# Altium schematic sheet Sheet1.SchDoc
size A4
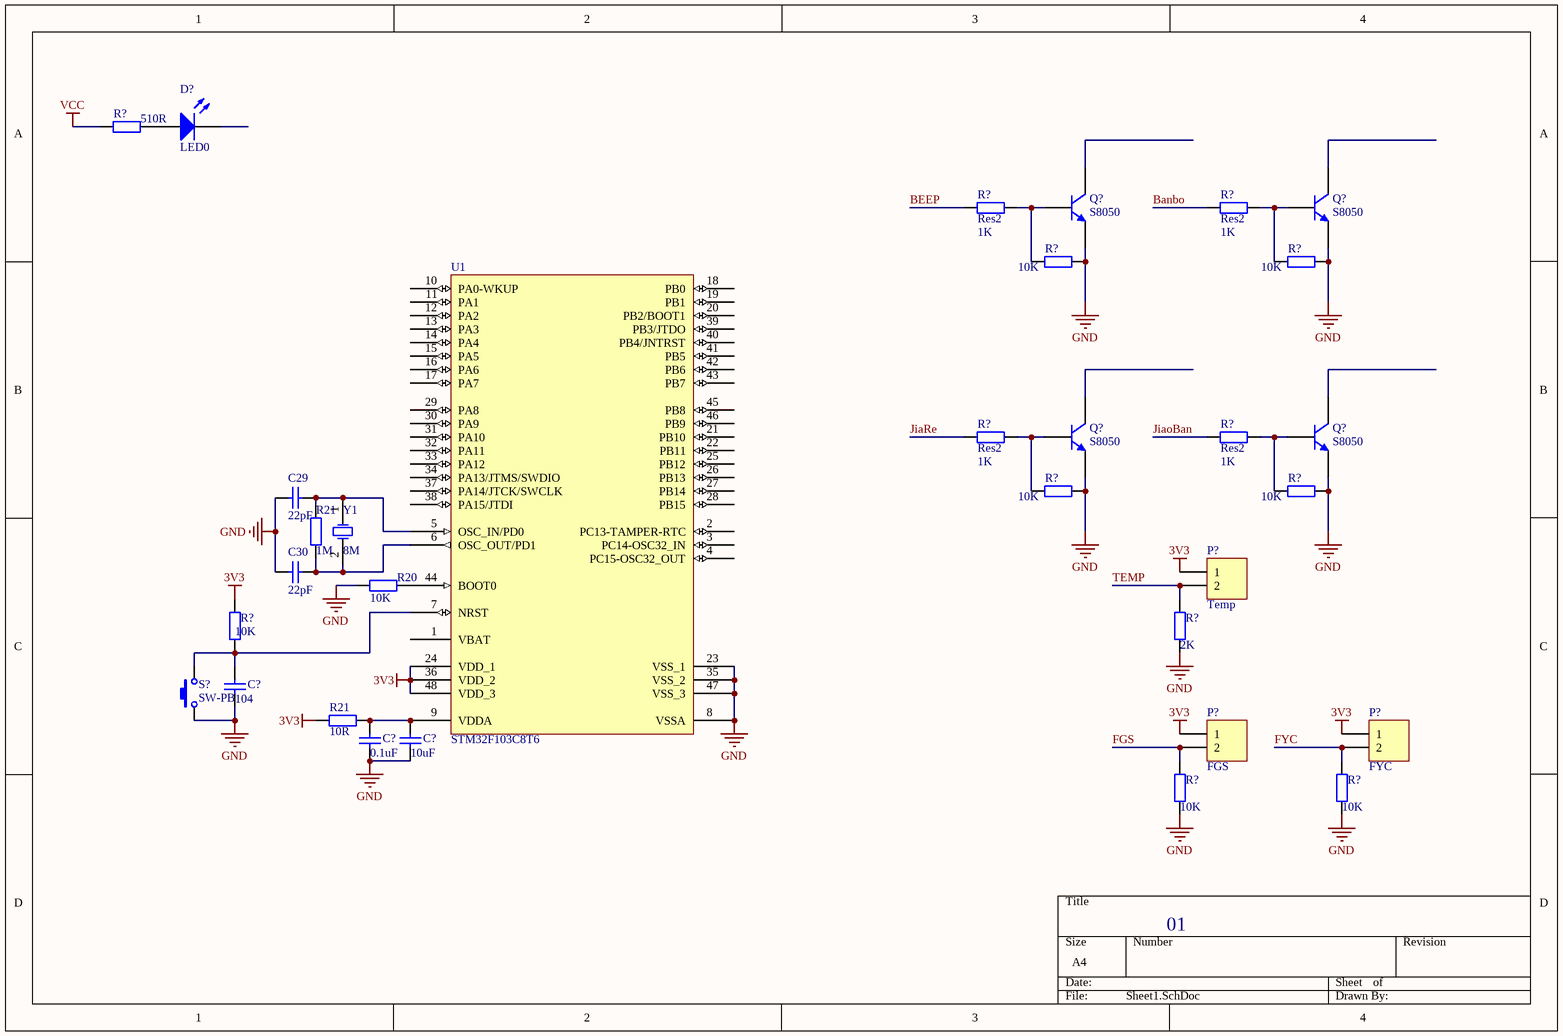
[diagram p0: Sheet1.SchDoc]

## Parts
(Parts that share a designator on the sheet are numbered #1, #2 ... from top to bottom, then left to right.)
C29  value 22pF  [0805_C]  (hidden comment: Cap)
C30  value 22pF  [0805_C]  (hidden comment: Cap)
C?#1  value 104  [0805_C]  (hidden comment: Cap)
C?#2  value 0.1uF  [0805_C]  (hidden comment: Cap)
C?#3  value 10uF  [0805_C]  (hidden comment: Cap)
D?  LED0  [0805_R]
P?#1  Temp  [HDR1X2]
P?#2  FGS  [HDR1X2]
P?#3  FYC  [HDR1X2]
Q?#1  S8050  [SOT23-3]
Q?#2  S8050  [SOT23-3]
Q?#3  S8050  [SOT23-3]
Q?#4  S8050  [SOT23-3]
R20  value 10K  [0805_R]  (hidden comment: Res2)
R21#1  value 1M  [0805_R]  (hidden comment: Res2)
R21#2  value 10R  [0805_R]  (hidden comment: Res2)
R?#1  value 510R  [0805_R]  (hidden comment: Res2)
R?#2  Res2  value 1K  [0805_R]
R?#3  Res2  value 1K  [0805_R]
R?#4  value 10K  [0805_R]  (hidden comment: Res2)
R?#5  value 10K  [0805_R]  (hidden comment: Res2)
R?#6  Res2  value 1K  [0805_R]
R?#7  Res2  value 1K  [0805_R]
R?#8  value 10K  [0805_R]  (hidden comment: Res2)
R?#9  value 10K  [0805_R]  (hidden comment: Res2)
R?#10  value 10K  [0805_R]  (hidden comment: Res2)
R?#11  value 2K  [0805_R]  (hidden comment: Res2)
R?#12  value 10K  [0805_R]  (hidden comment: Res2)
R?#13  value 10K  [0805_R]  (hidden comment: Res2)
S?  SW-PB  [KEY]
U1  STM32F103C8T6  [LQFP-48]
Y1  8M  [XTAL_US]

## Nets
3V3: P?#1.1 P?#2.1 P?#3.1 R21#2.1 R?#10.2 U1.24(VDD_1) U1.36(VDD_2) U1.48(VDD_3)
GND: C29.1 C30.1 C?#1.2 C?#2.1 C?#3.1 Q?#1.1(E) Q?#2.1(E) Q?#3.1(E) Q?#4.1(E) R20.1 R?#4.2 R?#5.2 R?#8.2 R?#9.2 R?#11.1 R?#12.1 R?#13.1 S?.1 U1.8(VSSA) U1.23(VSS_1) U1.35(VSS_2) U1.47(VSS_3)
VCC: R?#1.1
Banbo: R?#3.2
BEEP: R?#2.2
FGS: P?#2.2 R?#12.2
FYC: P?#3.2 R?#13.2
JiaoBan: R?#7.2
JiaRe: R?#6.2
TEMP: P?#1.2 R?#11.2
NetC29_2: C29.2 R21#1.1 U1.5(OSC_IN/PD0) Y1.1(OSC1)
NetC30_2: C30.2 R21#1.2 U1.6(OSC_OUT/PD1) Y1.2(OSC2)
NetC?#1_1: C?#1.1 R?#10.1 S?.2 U1.7(NRST)
NetC?#2_2: C?#2.2 C?#3.2 R21#2.2 U1.9(VDDA)
NetD?_1: D?.1(A) R?#1.2
NetQ?#1_2: Q?#1.2(B) R?#2.1 R?#4.1
NetQ?#2_2: Q?#2.2(B) R?#3.1 R?#5.1
NetQ?#3_2: Q?#3.2(B) R?#6.1 R?#8.1
NetQ?#4_2: Q?#4.2(B) R?#7.1 R?#9.1
NetR20_2: R20.2 U1.44(BOOT0)

Not connected (* = marked no-connect by the designer): D? 2(K); Q?#1 3(C); Q?#2 3(C); Q?#3 3(C); Q?#4 3(C); U1 1(VBAT) 2(PC13-TAMPER-RTC) 3(PC14-OSC32_IN) 4(PC15-OSC32_OUT) 10(PA0-WKUP) 11(PA1) 12(PA2) 13(PA3) 14(PA4) 15(PA5) 16(PA6) 17(PA7) 18(PB0) 19(PB1) 20(PB2/BOOT1) 21(PB10) 22(PB11) 25(PB12) 26(PB13) 27(PB14) 28(PB15) 29(PA8) 30(PA9) 31(PA10) 32(PA11) 33(PA12) 34(PA13/JTMS/SWDIO) 37(PA14/JTCK/SWCLK) 38(PA15/JTDI) 39(PB3/JTDO) 40(PB4/JNTRST) 41(PB5) 42(PB6) 43(PB7) 45(PB8) 46(PB9)

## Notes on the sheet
- 01

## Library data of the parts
C29 C30 C?#1-C?#3 = Cap: Capacitor
D? = LED0: Typical INFRARED GaAs LED
P?#1-P?#3 = Header 2: Header, 2-Pin
Q?#1-Q?#4 = 2N3904: NPN General Purpose Amplifier
R20 R21#1 R21#2 R?#1-R?#13 = Res2: Resistor
S? = SW-PB: Switch
Y1 = XTAL: Crystal Oscillator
